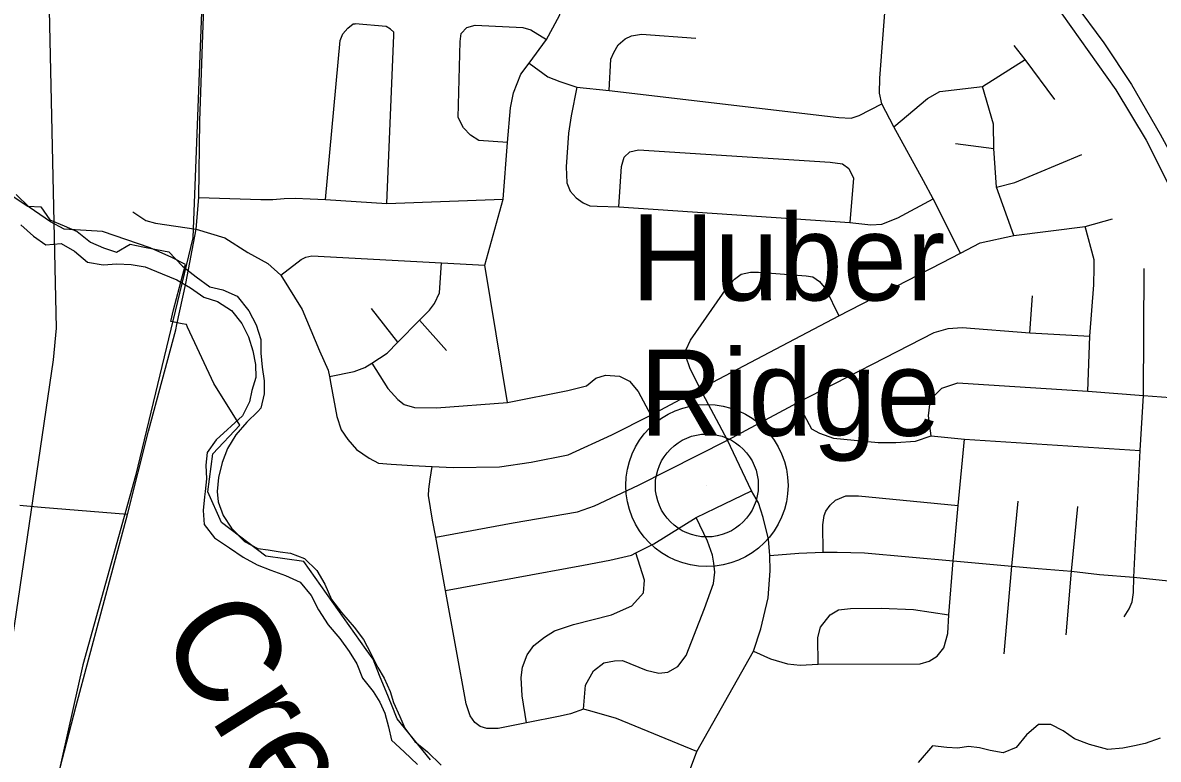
# Model space of a CAD drawing. Extents: x 0 to 34, y 0 to 22.
# Drawn here: x 27.434 to 28.475, y 5.077 to 5.753 of the extents above; entities that cross this region are included whole.
import ezdxf

# ---------------------------------------------------------------- set-up
doc = ezdxf.new("R2010")
doc.units = 0
for name, color, linetype in [('GM_X_Corporation', 7, 'Continuous'), ('GM_X_County_Road', 7, 'Continuous'), ('GM_X_Interstate_Route', 7, 'Continuous'), ('GM_X_Major_River', 7, 'Continuous'), ('GM_X_Major_River_Text', 7, 'Continuous'), ('GM_X_Minor_River', 7, 'Continuous'), ('GM_X_Rail_Line', 7, 'Continuous'), ('GM_X_State_Route', 7, 'Continuous'), ('GM_X_Township_Road', 7, 'Continuous'), ('GM_X_Unincorporated', 7, 'Continuous'), ('GM_X_Unincorporated_Location', 7, 'Continuous'), ('GM_X_Unincorporated_Text', 7, 'Continuous')]:
    doc.layers.add(name, color=color, linetype=linetype)

msp = doc.modelspace()

# ---------------------------------------------------------------- linework, layer by layer
at = {"layer": 'GM_X_Corporation'}
msp.add_lwpolyline([(27.8073, 5.0767), (27.7768, 5.1142), (27.7715, 5.1274), (27.7666, 5.1395), (27.7613, 5.1526), (27.7563, 5.1651), (27.7547, 5.169), (27.7484, 5.1779), (27.6911, 5.2586), (27.6564, 5.2635), (27.6158, 5.2942), (27.6031, 5.3224), (27.6079, 5.3573), (27.6326, 5.3836), (27.6088, 5.4218), (27.5847, 5.4735), (27.5836, 5.4759), (27.5797, 5.4767), (27.5693, 5.4788), (27.5718, 5.4893), (27.5827, 5.531), (27.5701, 5.5373), (27.5505, 5.5464), (27.5068, 5.5612), (27.4714, 5.5634), (27.4589, 5.5701), (27.4394, 5.5837), (27.4276, 5.5952)], dxfattribs=at)
at = {"layer": 'GM_X_County_Road'}
msp.add_line((27.5296, 5.3017), (27.4506, 5.3082), dxfattribs=at)
msp.add_lwpolyline([(27.4506, 5.3082), (27.4338, 5.3096), (27.4309, 5.3098)], dxfattribs=at)
at = {"layer": 'GM_X_Interstate_Route'}
for points in [[(28.2272, 5.9224), (28.235, 5.9164), (28.2736, 5.8833), (28.308, 5.851), (28.3462, 5.8098), (28.378, 5.7724), (28.4356, 5.6912), (28.4633, 5.6449), (28.4952, 5.5818), (28.5056, 5.5585), (28.5181, 5.5286), (28.5278, 5.5014), (28.5396, 5.4644), (28.549, 5.4299), (28.5567, 5.3977), (28.5611, 5.3773), (28.5657, 5.3503), (28.5694, 5.3196), (28.5734, 5.2922), (28.5751, 5.2643)], [(28.3973, 5.771), (28.4245, 5.7342), (28.4499, 5.696), (28.4763, 5.6504), (28.4984, 5.6101), (28.5109, 5.5822), (28.5234, 5.5532), (28.5333, 5.5278), (28.5445, 5.4958), (28.555, 5.4616), (28.5631, 5.4302), (28.5693, 5.4017), (28.5726, 5.3819), (28.5776, 5.3567), (28.5829, 5.3276), (28.5857, 5.3017), (28.5888, 5.2694), (28.5894, 5.2543)]]:
    msp.add_lwpolyline(points, dxfattribs=at)
at = {"layer": 'GM_X_Major_River'}
for points in [[(27.4249, 5.5933), (27.4381, 5.5845), (27.4502, 5.584), (27.4585, 5.5718), (27.4714, 5.5665), (27.4835, 5.5611), (27.4956, 5.5515), (27.5077, 5.5462), (27.5194, 5.5423), (27.532, 5.5495), (27.5437, 5.5471), (27.5562, 5.5448), (27.5676, 5.5425), (27.5801, 5.5295), (27.5925, 5.5196), (27.605, 5.5104), (27.6171, 5.5077), (27.63, 5.5019), (27.6409, 5.4886), (27.6477, 5.4756), (27.6518, 5.4623), (27.6517, 5.4498), (27.6532, 5.4369), (27.655, 5.4244), (27.655, 5.4122), (27.6519, 5.3993)], [(27.4319, 5.5674), (27.4433, 5.5571), (27.4546, 5.5491), (27.4687, 5.5502), (27.4811, 5.5433), (27.4928, 5.533), (27.5072, 5.5306)], [(27.5072, 5.5306), (27.5198, 5.5317), (27.533, 5.5309), (27.5459, 5.5289), (27.5614, 5.5224), (27.5747, 5.517), (27.5875, 5.5097), (27.5996, 5.5009), (27.6121, 5.4971), (27.625, 5.4887), (27.6344, 5.4768), (27.6404, 5.4647), (27.6445, 5.4517), (27.6468, 5.4392), (27.6471, 5.4274), (27.6436, 5.4153), (27.6413, 5.4051), (27.6351, 5.3922), (27.6108, 5.3703), (27.6027, 5.3585), (27.6015, 5.3468), (27.6019, 5.3343), (27.6008, 5.3227)], [(27.6519, 5.3993), (27.649, 5.396), (27.6389, 5.3865), (27.629, 5.3748), (27.6213, 5.3623), (27.6163, 5.3494), (27.6129, 5.3357), (27.6117, 5.3228), (27.6128, 5.3133), (27.6172, 5.3008), (27.6248, 5.289), (27.6369, 5.2768), (27.649, 5.2706), (27.6584, 5.2694), (27.6694, 5.2675)], [(27.6008, 5.3227), (27.6003, 5.318), (27.5991, 5.3054), (27.5998, 5.2925), (27.6092, 5.2803), (27.6232, 5.2711), (27.6356, 5.2627), (27.6485, 5.2554), (27.661, 5.2505), (27.6743, 5.2458), (27.6879, 5.2397), (27.6981, 5.2275), (27.7048, 5.2142), (27.7135, 5.2005), (27.7244, 5.1879), (27.7327, 5.1761), (27.7398, 5.1647), (27.7451, 5.1517), (27.7549, 5.1392), (27.7609, 5.1296), (27.7654, 5.1194), (27.7688, 5.1068), (27.7717, 5.0947), (27.7831, 5.084), (27.7955, 5.0725)], [(27.6694, 5.2675), (27.6789, 5.2663), (27.6918, 5.2613), (27.7031, 5.2503), (27.7106, 5.2377), (27.7166, 5.2236), (27.7257, 5.2118), (27.7374, 5.1985), (27.746, 5.187), (27.7528, 5.1741), (27.7592, 5.1615), (27.7648, 5.1516), (27.7704, 5.1395), (27.7734, 5.1292), (27.7791, 5.1163), (27.7839, 5.1056), (27.793, 5.0934), (27.8047, 5.0839), (27.8171, 5.0717)]]:
    msp.add_lwpolyline(points, dxfattribs=at)
at = {"layer": 'GM_X_Minor_River'}
msp.add_lwpolyline([(28.4762, 5.0966), (28.4624, 5.0918), (28.4526, 5.0896), (28.4419, 5.0875), (28.4282, 5.0861), (28.4116, 5.0908), (28.3976, 5.0959), (28.3874, 5.1032), (28.3761, 5.109), (28.3647, 5.1091), (28.3536, 5.0997), (28.3444, 5.088), (28.3322, 5.0832), (28.3204, 5.0852), (28.3106, 5.0876), (28.3007, 5.0889), (28.2909, 5.0874), (28.2806, 5.0879), (28.2677, 5.0896), (28.2543, 5.0741)], dxfattribs=at)
at = {"layer": 'GM_X_Rail_Line'}
for points in [[(26.5612, 3.3841), (26.5629, 3.3871), (26.6048, 3.434), (26.658, 3.4848), (27.0231, 3.755), (27.1106, 3.8337), (27.1525, 3.887), (27.1994, 3.9542), (27.2298, 4.0138), (27.259, 4.0938), (27.2717, 4.1673), (27.2907, 4.2828), (27.3324, 4.5642), (27.3731, 4.841), (27.4618, 5.4436), (27.4644, 5.4727), (27.4529, 6.0004), (27.4552, 6.6706), (27.4619, 6.8197), (27.4824, 7.181), (27.4896, 7.3031), (27.5213, 7.8422), (27.5447, 8.1693), (27.5992, 8.3999)], [(27.4824, 7.181), (27.6143, 6.7182), (27.6266, 6.646), (27.6291, 6.4258), (27.6038, 5.9295), (27.5895, 5.5554), (27.5368, 5.337), (27.4888, 5.1639), (27.437, 4.9331), (27.4309, 4.8441), (27.4259, 4.5594), (27.3324, 4.5642)]]:
    msp.add_lwpolyline(points, dxfattribs=at)
at = {"layer": 'GM_X_State_Route'}
for points in [[(27.5749, 5.4758), (27.5831, 5.5135), (27.5925, 5.5633), (27.5949, 5.5924), (27.596, 5.6626), (27.5989, 5.7504), (27.6019, 5.8287)], [(27.5166, 5.2529), (27.5296, 5.3017), (27.5489, 5.378), (27.5739, 5.4709), (27.5749, 5.4758)], [(27.4288, 4.7879), (27.4313, 4.8376), (27.4363, 4.9087), (27.4436, 4.9566), (27.4572, 5.0284), (27.4826, 5.1262), (27.5166, 5.2529)]]:
    msp.add_lwpolyline(points, dxfattribs=at)
at = {"layer": 'GM_X_Township_Road'}
for p, q in [((28.2886, 5.642), (28.3239, 5.6373)), ((28.3569, 5.4682), (28.3591, 5.5021)), ((27.7773, 5.4598), (27.7532, 5.4907)), ((27.8219, 5.4521), (27.7973, 5.48))]:
    msp.add_line(p, q, dxfattribs=at)
for points in [[(27.8779, 5.4043), (27.8571, 5.5303), (27.8741, 5.591), (27.878, 5.6428), (27.8806, 5.6746), (27.8834, 5.6884), (27.8902, 5.7055), (27.8979, 5.7157), (27.9137, 5.7373), (27.9195, 5.7479), (27.9259, 5.7598), (27.9288, 5.772), (27.9297, 5.7845), (27.9304, 5.8016)], [(28.2592, 5.6078), (28.2322, 5.6573), (28.2212, 5.6783), (28.2191, 5.688), (28.2193, 5.702), (28.2253, 5.7823)], [(27.7111, 5.5907), (27.7247, 5.7365), (27.727, 5.7426), (27.7316, 5.7478), (27.7366, 5.7516), (27.7382, 5.7516)], [(27.7673, 5.587), (27.7737, 5.7412), (27.7738, 5.7439), (27.7708, 5.7469), (27.7666, 5.7493), (27.7382, 5.7516)], [(27.878, 5.6428), (27.8516, 5.6447), (27.8439, 5.6495), (27.8375, 5.6563), (27.8327, 5.6659), (27.8346, 5.7354), (27.8355, 5.7427), (27.8407, 5.7482), (27.8484, 5.7505), (27.8921, 5.7482), (27.8992, 5.7463), (27.9137, 5.7373)], [(27.9712, 5.6907), (27.9728, 5.7193), (27.9754, 5.7254), (27.9793, 5.7325), (27.9857, 5.7379), (27.9915, 5.7408), (28.0008, 5.7421), (28.0506, 5.7386)], [(28.3797, 5.6824), (28.3524, 5.719), (28.3424, 5.7317)], [(27.8979, 5.7157), (27.915, 5.7032), (27.9259, 5.6987), (27.9416, 5.6936), (27.9712, 5.6907), (28.1817, 5.6658), (28.1931, 5.6653), (28.2003, 5.6675), (28.2212, 5.6783)], [(28.2322, 5.6573), (28.263, 5.6832), (28.2742, 5.6897), (28.3135, 5.6943), (28.3524, 5.719)], [(27.9416, 5.6936), (27.9362, 5.6672), (27.9339, 5.6514), (27.9317, 5.6206), (27.9323, 5.6058), (27.9355, 5.5981), (27.941, 5.592), (27.9474, 5.5875), (27.9535, 5.5849), (27.9603, 5.5846), (27.9799, 5.5839), (28.1919, 5.5695), (28.211, 5.5673), (28.221, 5.568), (28.2357, 5.5739), (28.2681, 5.5912)], [(28.3422, 5.5577), (28.3263, 5.6019), (28.3239, 5.6373), (28.3235, 5.6597), (28.3135, 5.6943)], [(27.9799, 5.5839), (27.9825, 5.6209), (27.985, 5.6293), (27.99, 5.6343), (27.9981, 5.6362), (28.1738, 5.6248), (28.1852, 5.6233), (28.1908, 5.6189), (28.1952, 5.61), (28.1919, 5.5695)], [(28.3263, 5.6019), (28.3429, 5.6063), (28.4045, 5.6318)], [(28.2932, 5.5415), (28.2681, 5.5912), (28.2592, 5.6078)], [(27.5949, 5.5924), (27.6517, 5.5905), (27.6627, 5.5905), (27.6732, 5.5916), (27.6834, 5.5919), (27.6972, 5.5913)], [(27.6972, 5.5913), (27.7111, 5.5907), (27.7673, 5.587), (27.8741, 5.591)], [(27.5346, 5.5793), (27.5465, 5.5712), (27.5552, 5.5688), (27.5925, 5.5633)], [(28.276, 5.5326), (28.2932, 5.5415), (28.3112, 5.5507), (28.3422, 5.5577), (28.4074, 5.5658), (28.4325, 5.5728)], [(27.5925, 5.5633), (27.6188, 5.5554), (27.6398, 5.542), (27.6583, 5.5318), (27.6701, 5.5213), (27.6897, 5.4896), (27.7056, 5.4518), (27.7137, 5.4342), (27.7147, 5.4282), (27.7159, 5.4212), (27.7216, 5.3915), (27.7256, 5.3793), (27.7316, 5.3705), (27.7395, 5.3613), (27.7511, 5.3535), (27.7598, 5.3488), (27.7712, 5.3479), (27.791, 5.3465), (27.8088, 5.3457), (27.8282, 5.3449), (27.8707, 5.3454), (27.8997, 5.3496), (27.9336, 5.3564), (27.9736, 5.3746), (28.0093, 5.3929), (28.0546, 5.417), (28.1816, 5.484), (28.276, 5.5326)], [(28.41, 5.4149), (28.4118, 5.4652), (28.4155, 5.5124), (28.4159, 5.5282), (28.4159, 5.5352), (28.4074, 5.5658)], [(27.6701, 5.5213), (27.6888, 5.5356), (27.693, 5.5378), (27.6987, 5.5389), (27.8176, 5.5325), (27.8571, 5.5303)], [(27.7147, 5.4282), (27.7373, 5.4327), (27.7472, 5.4364), (27.7535, 5.4406), (27.7675, 5.4498), (27.7773, 5.4598), (27.7973, 5.48), (27.8064, 5.4892), (27.811, 5.4952), (27.8157, 5.505), (27.8176, 5.5325)], [(28.0546, 5.417), (28.045, 5.4361), (28.0417, 5.4461), (28.0417, 5.4529), (28.0456, 5.4617), (28.0799, 5.5107), (28.0861, 5.5174), (28.0922, 5.5221), (28.1007, 5.524), (28.1082, 5.524), (28.1519, 5.5207), (28.1578, 5.5196), (28.1641, 5.5155), (28.1699, 5.5083), (28.1816, 5.484)], [(28.4432, 5.2079), (28.4478, 5.2153), (28.4505, 5.2217), (28.4518, 5.2302), (28.4522, 5.2442), (28.4578, 5.3605), (28.4611, 5.4108), (28.4616, 5.5272)], [(27.8122, 5.281), (27.883, 5.294), (27.9421, 5.3042), (27.9577, 5.3097), (27.9981, 5.3285), (28.0795, 5.37), (28.1441, 5.4045), (28.2692, 5.4685), (28.2818, 5.4722), (28.2947, 5.4733), (28.3569, 5.4682), (28.4118, 5.4652)], [(27.7535, 5.4406), (27.7683, 5.4171), (27.7773, 5.4071), (27.7833, 5.4025), (27.7927, 5.3997), (27.8129, 5.3994), (27.8779, 5.4043), (27.9332, 5.4153), (27.9503, 5.4196), (27.959, 5.4266), (27.9677, 5.4295), (27.9806, 5.4286), (27.9898, 5.4241), (27.9977, 5.4145), (28.0093, 5.3929)], [(28.0771, 4.8672), (28.0745, 4.8754), (28.0688, 4.8932), (28.0436, 4.9743), (28.0402, 4.9909), (28.0391, 5.0066), (28.0399, 5.0289), (28.0416, 5.0522), (28.0438, 5.0638), (28.0514, 5.0842), (28.1034, 5.1764), (28.1102, 5.1968), (28.1169, 5.2253), (28.1188, 5.25), (28.1184, 5.2641), (28.1171, 5.2791), (28.1123, 5.299), (28.108, 5.3125), (28.1017, 5.3235), (28.0795, 5.37), (28.0546, 5.417)], [(28.2663, 5.3738), (28.2638, 5.3921), (28.265, 5.4025), (28.2683, 5.4095), (28.2762, 5.4174), (28.2908, 5.4224), (28.3049, 5.4216), (28.41, 5.4149), (28.4611, 5.4108), (28.5023, 5.4079)], [(28.1441, 5.4045), (28.1499, 5.3929), (28.1566, 5.3804), (28.1641, 5.3763), (28.1769, 5.3717), (28.2177, 5.3676), (28.2339, 5.3676), (28.2521, 5.3688), (28.2663, 5.3738), (28.297, 5.3709), (28.4578, 5.3605)], [(28.1034, 5.1764), (28.1192, 5.1694), (28.1346, 5.1648), (28.1462, 5.1634), (28.1628, 5.1644), (28.2563, 5.1648), (28.2646, 5.1673), (28.2717, 5.1719), (28.2779, 5.1793), (28.2816, 5.1926), (28.2825, 5.2097), (28.2866, 5.2591), (28.2912, 5.3098), (28.297, 5.3709)], [(28.0514, 5.0842), (27.9778, 5.1147), (27.9535, 5.1216), (27.9477, 5.1232), (27.9356, 5.1189), (27.9261, 5.1167), (27.8955, 5.1106), (27.8693, 5.1053), (27.8591, 5.1054), (27.853, 5.1074), (27.8481, 5.1109), (27.8436, 5.117), (27.84, 5.1281), (27.821, 5.2321), (27.8122, 5.281), (27.8093, 5.2965), (27.8054, 5.319), (27.8059, 5.325), (27.8071, 5.3341), (27.8088, 5.3457)], [(27.821, 5.2321), (27.9475, 5.2551), (27.9719, 5.2597), (27.9917, 5.2644), (27.9955, 5.2664), (28.012, 5.2748), (28.051, 5.2988), (28.0687, 5.3075), (28.1017, 5.3235)], [(28.1674, 5.267), (28.167, 5.2921), (28.1682, 5.3007), (28.1697, 5.3048), (28.1736, 5.3102), (28.1786, 5.3148), (28.1881, 5.3189), (28.1998, 5.3189), (28.2912, 5.3098)], [(28.3334, 5.1739), (28.3404, 5.2543), (28.346, 5.314)], [(27.9477, 5.1232), (27.9496, 5.1451), (27.9568, 5.1582), (27.9663, 5.1655), (27.9759, 5.1676), (27.9833, 5.1678), (28.0052, 5.1589), (28.0167, 5.1561), (28.0249, 5.1572), (28.0342, 5.1623), (28.0417, 5.1723), (28.0585, 5.2155), (28.0668, 5.2383), (28.0679, 5.2487), (28.067, 5.257), (28.066, 5.2645), (28.0614, 5.2772), (28.051, 5.2988)], [(28.3901, 5.1914), (28.3951, 5.2498), (28.4009, 5.309)], [(27.8955, 5.1106), (27.8913, 5.1354), (27.8904, 5.1521), (27.8917, 5.1616), (27.896, 5.173), (27.9022, 5.1816), (27.9118, 5.1891), (27.921, 5.1951), (27.9385, 5.2009), (27.9732, 5.2096), (27.9919, 5.218), (28.0026, 5.2297), (28.0036, 5.2415), (27.9955, 5.2664)], [(28.1184, 5.2641), (28.1449, 5.2662), (28.1674, 5.267), (28.1803, 5.267), (28.2052, 5.2666), (28.2866, 5.2591), (28.3404, 5.2543), (28.3645, 5.2521), (28.3951, 5.2498), (28.4208, 5.2467), (28.4522, 5.2442), (28.484, 5.2408), (28.4933, 5.2404), (28.502, 5.2419), (28.5093, 5.2444), (28.517, 5.2491)], [(28.1628, 5.1644), (28.1624, 5.1889), (28.1649, 5.1985), (28.1736, 5.2097), (28.1815, 5.2142), (28.1923, 5.2155), (28.2206, 5.2159), (28.2501, 5.2147), (28.2825, 5.2097)]]:
    msp.add_lwpolyline(points, dxfattribs=at)
at = {"layer": 'GM_X_Unincorporated'}
for radius in [0.0744, 0.0472]:
    msp.add_circle((28.0607, 5.3283), radius, dxfattribs=at)
at = {"layer": 'GM_X_Unincorporated_Location'}
msp.add_line((28.0607, 5.3283), (28.0607, 5.3283), dxfattribs=at)

# ---------------------------------------------------------------- texts
at = {"layer": 'GM_X_Major_River_Text'}
msp.add_text('Creek', height=0.0947, rotation=302.2062, dxfattribs=at).set_placement((27.5562, 5.1918))
at = {"layer": 'GM_X_Unincorporated_Text'}
for s, p in [('Huber', (27.9915, 5.498)), ('Ridge', (27.999, 5.3739))]:
    msp.add_text(s, height=0.07898, rotation=0, dxfattribs=at).set_placement(p)

doc.saveas('drawing.dxf')
